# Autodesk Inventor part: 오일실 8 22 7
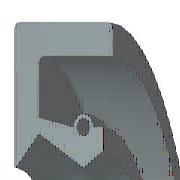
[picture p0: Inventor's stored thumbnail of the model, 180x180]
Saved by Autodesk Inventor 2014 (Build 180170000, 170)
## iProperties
IsCustomPart: 1
Created: 2012-02
Part Number: 오일실 8 22 7
Material: 고무
Description: 오일-실
Document SubType Name: Modeling
Standard: KS B 2804
Designer: mduedu
Standards Organization: KS
Language: ko-KR
Size Designation: D - 8 22 7
Categories: <MemberInstance><Categories><Category DisplayName="샤프트 부품" InternalName="7f7aeb1f-a693-4053-b835-cee3144e0d98" Mnemonic="SHFT"><Category DisplayName="실링" Intern
Density: 0.93 g/cm^3
Appearance: 고무 - 검은색 - 버전 1.1
Author: mduedu
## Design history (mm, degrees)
revolve "본체" stored, may be unused: angle "d17" = 90 deg
revolve "스프링1" stored, may be unused: angle "d18" = 90 deg
body "Solid1"
sketch "스케치1"
  geometry: L1 (0, 11)-(7, 11); L2 (7, 9.25)-(1.75, 9.25); L3 (1.75, 5.75)-(4.9, 4); L4 (4.9, 4)-(0, 4); L5 (0, 0)-(9.586, 0) reference; L6 (4.9, 4)-(6.3, 4.875); L7 (0, 18)-(0, -3) reference; L8 (-1.941, 0)-(11.507, 0) reference; L9 (4.2, 6.1)-(1.75, 6.59); L10 (1.75, 6.59)-(1.75, 9.25); L11 (0, 11)-(0, 4.088); L12 (4.9, 4)-(0, 4); L13 (1.75, 5.75)-(0.152, 4.028); L14 (7, 11)-(7, 9.25); L15 (5.6, 6.1)-(6.3, 6.1); L16 (6.3, 6.1)-(6.3, 4.875); C1 r 0.455 at (4.9, 6.1); A1 r 0.7 centre (4.9, 6.1) between (5.6, 6.1) and (4.2, 6.1); A2 r 0.088 centre (0.088, 4.088) between (0, 4.088) and (0.152, 4.028); 1 further point
  constraints: 28 end point, 5 horizontal alignment, 5 point on line, 4 point on circle, 4 vertical alignment, 3 centre point, 3 tangent, 2 collinear, 2 horizontal, 2 perpendicular, 1 coincident, 1 parallel
  dimensions: "d0" = 22 diameter of L1 L5 (= SD2); "d1" = 1.75 distance of L1.end L2.start (= SD); "d2" = 0.91 diameter of C1 (= SPDI); "d3" = 1.4 diameter of A1 (= SPDA); "d4" = 8 diameter of L3.end L5 (= NND); "d5" = 11.5 diameter of L3.start L5 (= TKDM); "d7" = 13.18 diameter of L9.end L5 (= TKDM + 0.24 x SWDT); "d8" = 1.75 distance between parallel lines of L11 L10 (= SD); "d9" = 4.9 distance from line of L11 C1.centre (= SPDST); "d10" = 12.2 diameter of C1.centre L5 (= HLDM); "d11" = 0.0875 radius of A2 (= 0.25 x LAB); "d12" = 6.3 distance between parallel lines of L11 L16 (= SDI); "d13" = 9.75 diameter of L6.end L5 (= ABDM); "d14" = 7 distance from line of L11 L1.end (= SWDT)
fillet "모깎기1" dims "d6" = 0.3 (= RR)
other parameters: "SD2" = 22 [user parameter; used in 1 equation term], "SWDT" = 7 [user parameter; used in 2 equation terms], "RR" = 0.3 [user parameter; used in 1 equation term], "SD" = 1.75 [user parameter; used in 2 equation terms], "NND" = 8 [user parameter; used in 1 equation term], "SPDA" = 1.4 [user parameter; used in 1 equation term], "SPDI" = 0.91 [user parameter; used in 1 equation term], "TKDM" = 11.5 [user parameter; used in 2 equation terms], "HLDM" = 12.2 [user parameter; used in 1 equation term], "ABDM" = 9.75 [user parameter; used in 1 equation term], "SDI" = 6.3 [user parameter; used in 1 equation term], "SPDST" = 4.9 [user parameter; used in 1 equation term], "LAB" = 0.35 [user parameter; used in 1 equation term], "d15" = 0, "d16" = 0, "d19" = 0
